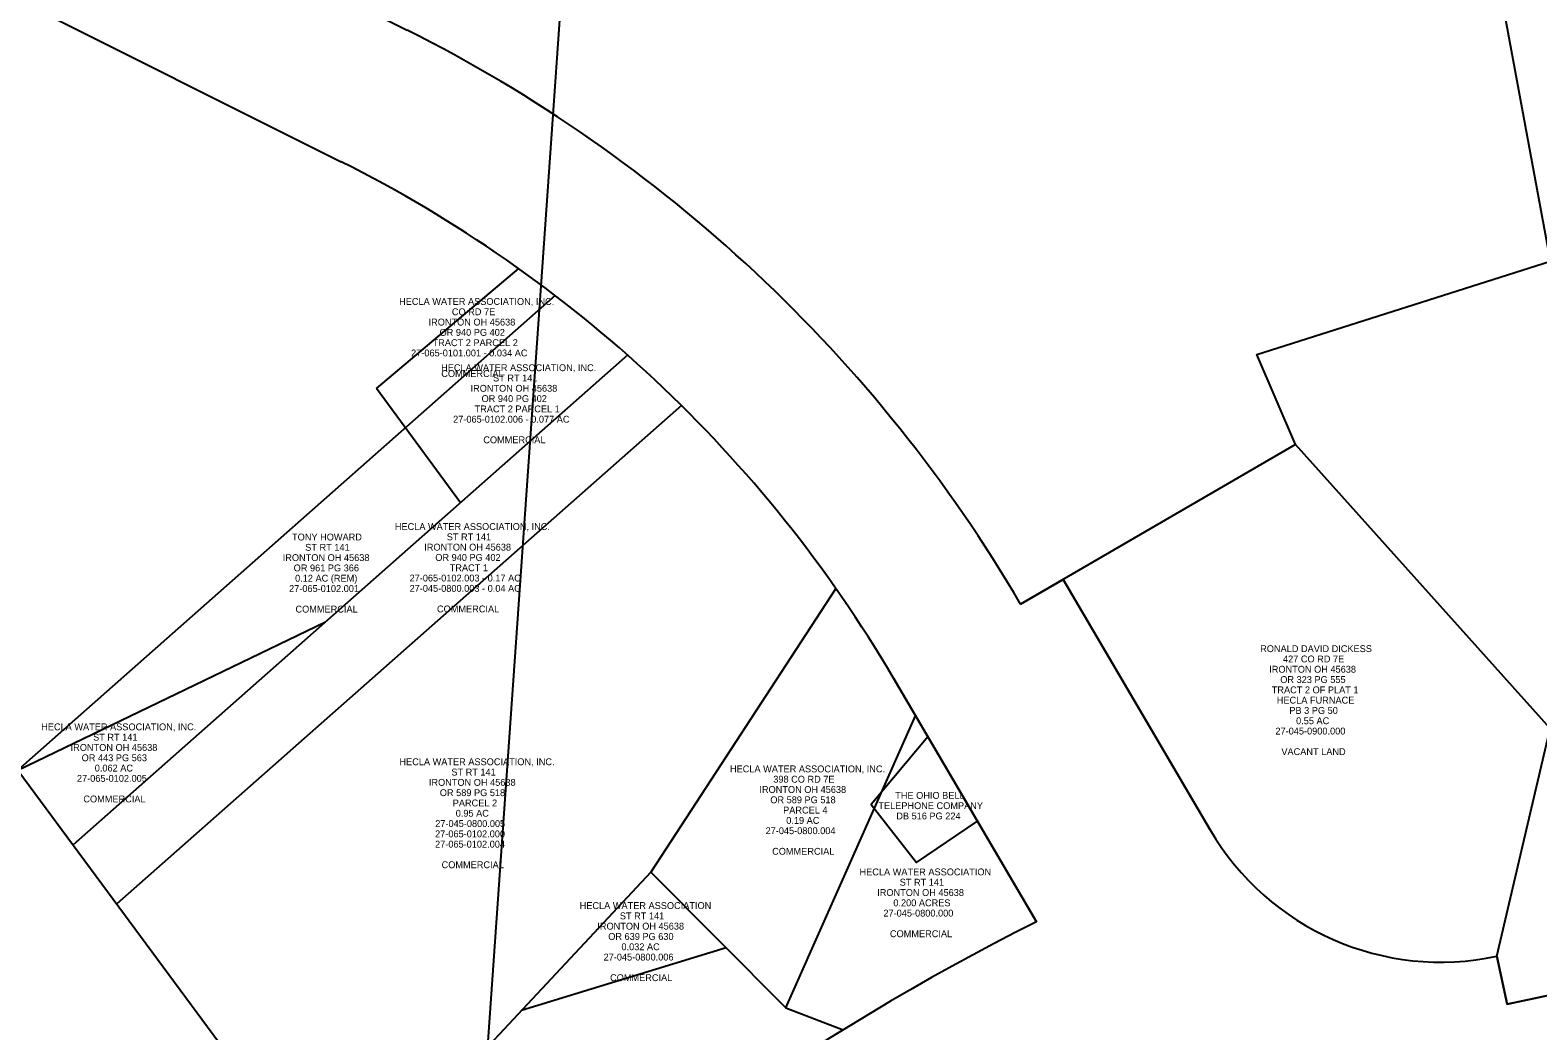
# Model space of a CAD drawing. Extents: x 1926695 to 1928303, y 198652 to 200926.
# Drawn here: x 1927197 to 1927812, y 199742 to 200150 of the extents above; entities that cross this region are included whole.
import ezdxf

# ---------------------------------------------------------------- set-up
doc = ezdxf.new("R2010")
doc.units = 0
for name, color, linetype in [('DV_X_Property_Line', 7, 'Continuous'), ('DV_X_Section_VMS_Line', 7, 'Continuous'), ('DV_X_Text', 7, 'Continuous'), ('RW_X_Esmt_U', 7, 'Continuous'), ('RW_X_Fee_RW', 7, 'Continuous')]:
    doc.layers.add(name, color=color, linetype=linetype)

msp = doc.modelspace()

# ---------------------------------------------------------------- linework, layer by layer
at = {"layer": 'DV_X_Property_Line'}
for p, q in [((1927054.38, 200231.23), (1927323.97, 200096.26)), ((1927338.26, 200003.84), (1927396.33, 200052.68)), ((1927411.18, 200041.69), (1927192.02, 199848.17)), ((1927440.7, 200017.37), (1927214.57, 199817.69)), ((1927372.55, 199957.19), (1927338.26, 200003.84)), ((1927462.61, 199996.88), (1927232.4, 199793.6)), ((1927713.01, 199980.89), (1927600.94, 199915.88)), ((1927678.22, 199823.76), (1927618.24, 199925.92)), ((1927525.66, 199922.17), (1927450.16, 199806.6)), ((1927192.02, 199848.17), (1927317.58, 199908.65)), ((1927607.41, 199786.36), (1927549.12, 199885.64)), ((1927505.27, 199751.18), (1927558.14, 199870.28)), ((1927192.02, 199848.17), (1927363.59, 199616.33)), ((1927450.16, 199806.6), (1927323.3, 199670.77)), ((1927450.16, 199806.6), (1927505.27, 199751.18)), ((1927480.84, 199775.75), (1927397.43, 199750.14)), ((1927505.27, 199751.18), (1927528.62, 199742.32))]:
    msp.add_line(p, q, dxfattribs=at)
for points in [[(1927795.13, 199772.28), (1927816.89, 199865.18), (1927713.01, 199980.89), (1927697.26, 200017.66), (1927817.06, 200055.74), (1927729.84, 200526.35), (1927673.87, 200524.47), (1927316.35, 200167.17)], [(1927856.83, 199765), (1927799.31, 199752.72), (1927795.13, 199772.28)]]:
    msp.add_lwpolyline(points, dxfattribs=at)
for centre, radius, start, end in [((1927080.88, 199610.74), 602.97, 30.4018, 63.404), ((1927080.89, 199610.75), 542.96, 30.41641, 63.40416), ((1927772.34, 199879.02), 109.15, 210.41641, 282.05144), ((1928078.57, 198850.88), 1047.43, 116.73228, 150.49325)]:
    msp.add_arc(centre, radius, start, end, dxfattribs=at)
at = {"layer": 'DV_X_Section_VMS_Line'}
msp.add_line((1927376.1, 199627.83), (1927467.32, 200926.12), dxfattribs=at)
at = {"layer": 'RW_X_Esmt_U'}
msp.add_lwpolyline([(1927563.11, 199861.81), (1927540, 199834.21), (1927558.47, 199810.57), (1927583.36, 199827.32)], dxfattribs=at)
at = {"layer": 'RW_X_Fee_RW'}
for p, q in [((1926922.48, 200364.37), (1927350.83, 200149.91)), ((1927054.38, 200231.23), (1927323.97, 200096.26)), ((1927549.12, 199885.64), (1927607.41, 199786.36))]:
    msp.add_line(p, q, dxfattribs=at)
for points in [[(1927600.94, 199915.88), (1927618.24, 199925.92), (1927678.22, 199823.76)], [(1927795.13, 199772.28), (1927799.31, 199752.72), (1927856.83, 199765)]]:
    msp.add_lwpolyline(points, dxfattribs=at)
for centre, radius, start, end in [((1927080.88, 199610.74), 602.97, 30.4018, 63.404), ((1927080.89, 199610.75), 542.96, 30.41641, 63.40416), ((1927772.34, 199879.02), 109.15, 210.41641, 282.05144), ((1928078.57, 198850.88), 1047.43, 116.73228, 150.49325)]:
    msp.add_arc(centre, radius, start, end, dxfattribs=at)

# ---------------------------------------------------------------- texts
at = {"layer": 'DV_X_Text'}
for s, p in [('HECLA WATER ASSOCIATION, INC.', (1927347.54, 200037.87)), ('CO RD 7E', (1927369.05, 200033.67)), ('IRONTON OH 45638', (1927359.54, 200029.47)), ('TRACT 2 PARCEL 2', (1927361.19, 200021.07)), ('OR 940 PG 402', (1927364.03, 200025.27)), ('27-065-0101.001 - 0.034 AC', (1927352.42, 200016.87)), ('COMMERCIAL', (1927364.73, 200008.47)), ('HECLA WATER ASSOCIATION, INC.', (1927364.67, 200010.86)), ('IRONTON OH 45638', (1927376.66, 200002.46)), ('ST RT 141', (1927385.84, 200006.66)), ('OR 940 PG 402', (1927381.15, 199998.26)), ('27-065-0102.006 - 0.077 AC', (1927369.55, 199989.86)), ('TRACT 2 PARCEL 1', (1927378.31, 199994.06)), ('COMMERCIAL', (1927381.86, 199981.46)), ('TONY HOWARD', (1927303.88, 199941.82)), ('HECLA WATER ASSOCIATION, INC.', (1927345.79, 199946.09)), ('ST RT 141', (1927366.96, 199941.89)), ('ST RT 141', (1927309.26, 199937.62)), ('IRONTON OH 45638', (1927357.79, 199937.69)), ('IRONTON OH 45638', (1927300.08, 199933.42)), ('OR 961 PG 366', (1927304.54, 199929.22)), ('OR 940 PG 402', (1927362.28, 199933.49)), ('TRACT 1', (1927368.17, 199929.29)), ('0.12 AC (REM)', (1927305.12, 199925.02)), ('27-065-0102.003 - 0.17 AC', (1927351.79, 199925.09)), ('27-065-0102.001', (1927302.66, 199920.82)), ('27-045-0800.003 - 0.04 AC', (1927351.79, 199920.89)), ('COMMERCIAL', (1927305.28, 199912.42)), ('COMMERCIAL', (1927362.98, 199912.49)), ('RONALD DAVID DICKESS', (1927698.62, 199896.3)), ('427 CO RD 7E', (1927707.92, 199892.1)), ('IRONTON OH 45638', (1927702.31, 199887.9)), ('TRACT 2 OF PLAT 1', (1927703.35, 199879.5)), ('OR 323 PG 555', (1927706.81, 199883.7)), ('HECLA FURNACE', (1927705.4, 199875.3)), ('PB 3 PG 50', (1927710.51, 199871.1)), ('0.55 AC', (1927713.26, 199866.9)), ('HECLA WATER ASSOCIATION, INC.', (1927201.6, 199864.41)), ('ST RT 141', (1927222.77, 199860.21)), ('27-045-0900.000', (1927704.84, 199862.7)), ('IRONTON OH 45638', (1927213.6, 199856.01)), ('VACANT LAND', (1927707.26, 199854.3)), ('OR 443 PG 563', (1927218.1, 199851.81)), ('HECLA WATER ASSOCIATION, INC.', (1927347.67, 199850.18)), ('27-065-0102.005', (1927216.18, 199843.41)), ('0.062 AC', (1927223.43, 199847.61)), ('IRONTON OH 45638', (1927359.67, 199841.78)), ('ST RT 141', (1927368.84, 199845.98)), ('HECLA WATER ASSOCIATION, INC.', (1927482.44, 199847.27)), ('398 CO RD 7E', (1927500.1, 199843.07)), ('OR 589 PG 518', (1927364.13, 199837.58)), ('IRONTON OH 45638', (1927494.43, 199838.87)), ('THE OHIO BELL', (1927549.82, 199836.48)), ('COMMERCIAL', (1927218.79, 199835.01)), ('PARCEL 2', (1927369.4, 199833.38)), ('OR 589 PG 518', (1927498.89, 199834.67)), ('PARCEL 4', (1927504.11, 199830.47)), ('TELEPHONE COMPANY', (1927542.95, 199832.28)), ('27-045-0800.005', (1927362.26, 199824.98)), ('0.95 AC', (1927370.61, 199829.18)), ('0.19 AC', (1927505.38, 199826.27)), ('DB 516 PG 224', (1927550.25, 199828.08)), ('27-065-0102.000', (1927362.2, 199820.78)), ('27-045-0800.004', (1927496.95, 199822.07)), ('27-065-0102.004', (1927362.19, 199816.58)), ('COMMERCIAL', (1927499.63, 199813.67)), ('COMMERCIAL', (1927364.86, 199808.18)), ('HECLA WATER ASSOCIATION', (1927535.26, 199805.26)), ('ST RT 141', (1927551.64, 199801.06)), ('IRONTON OH 45638', (1927542.47, 199796.86)), ('0.200 ACRES', (1927549.05, 199792.66)), ('HECLA WATER ASSOCIATION', (1927421.15, 199791.54)), ('ST RT 141', (1927437.53, 199787.34)), ('27-045-0800.000', (1927545, 199788.46)), ('IRONTON OH 45638', (1927428.35, 199783.14)), ('OR 639 PG 630', (1927432.8, 199778.94)), ('0.032 AC', (1927438.18, 199774.74)), ('COMMERCIAL', (1927547.66, 199780.06)), ('27-045-0800.006', (1927430.9, 199770.54)), ('COMMERCIAL', (1927433.55, 199762.14))]:
    msp.add_text(s, height=2.8, dxfattribs=at).set_placement(p)

doc.saveas('drawing.dxf')
